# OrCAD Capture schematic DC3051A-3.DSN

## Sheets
1 PAGE2: size A
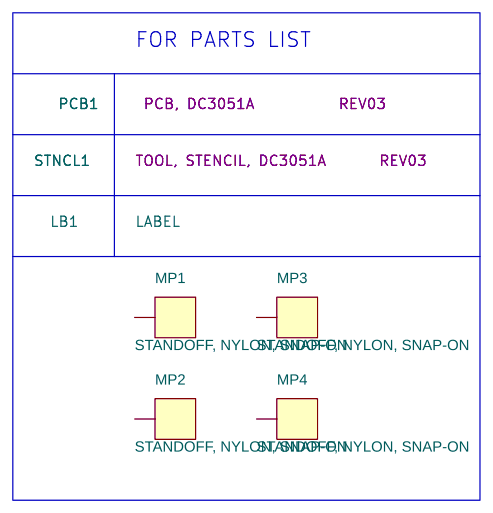
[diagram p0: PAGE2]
2 PAGE1: size Custom; title: Switched Capacitor Converter; company: ANALOG DEVICES; note: DEMO BOARD BILL OF MATERIALS; note: 20Vin,Dual 5A Step-Down DC/DC    Module    Regulator
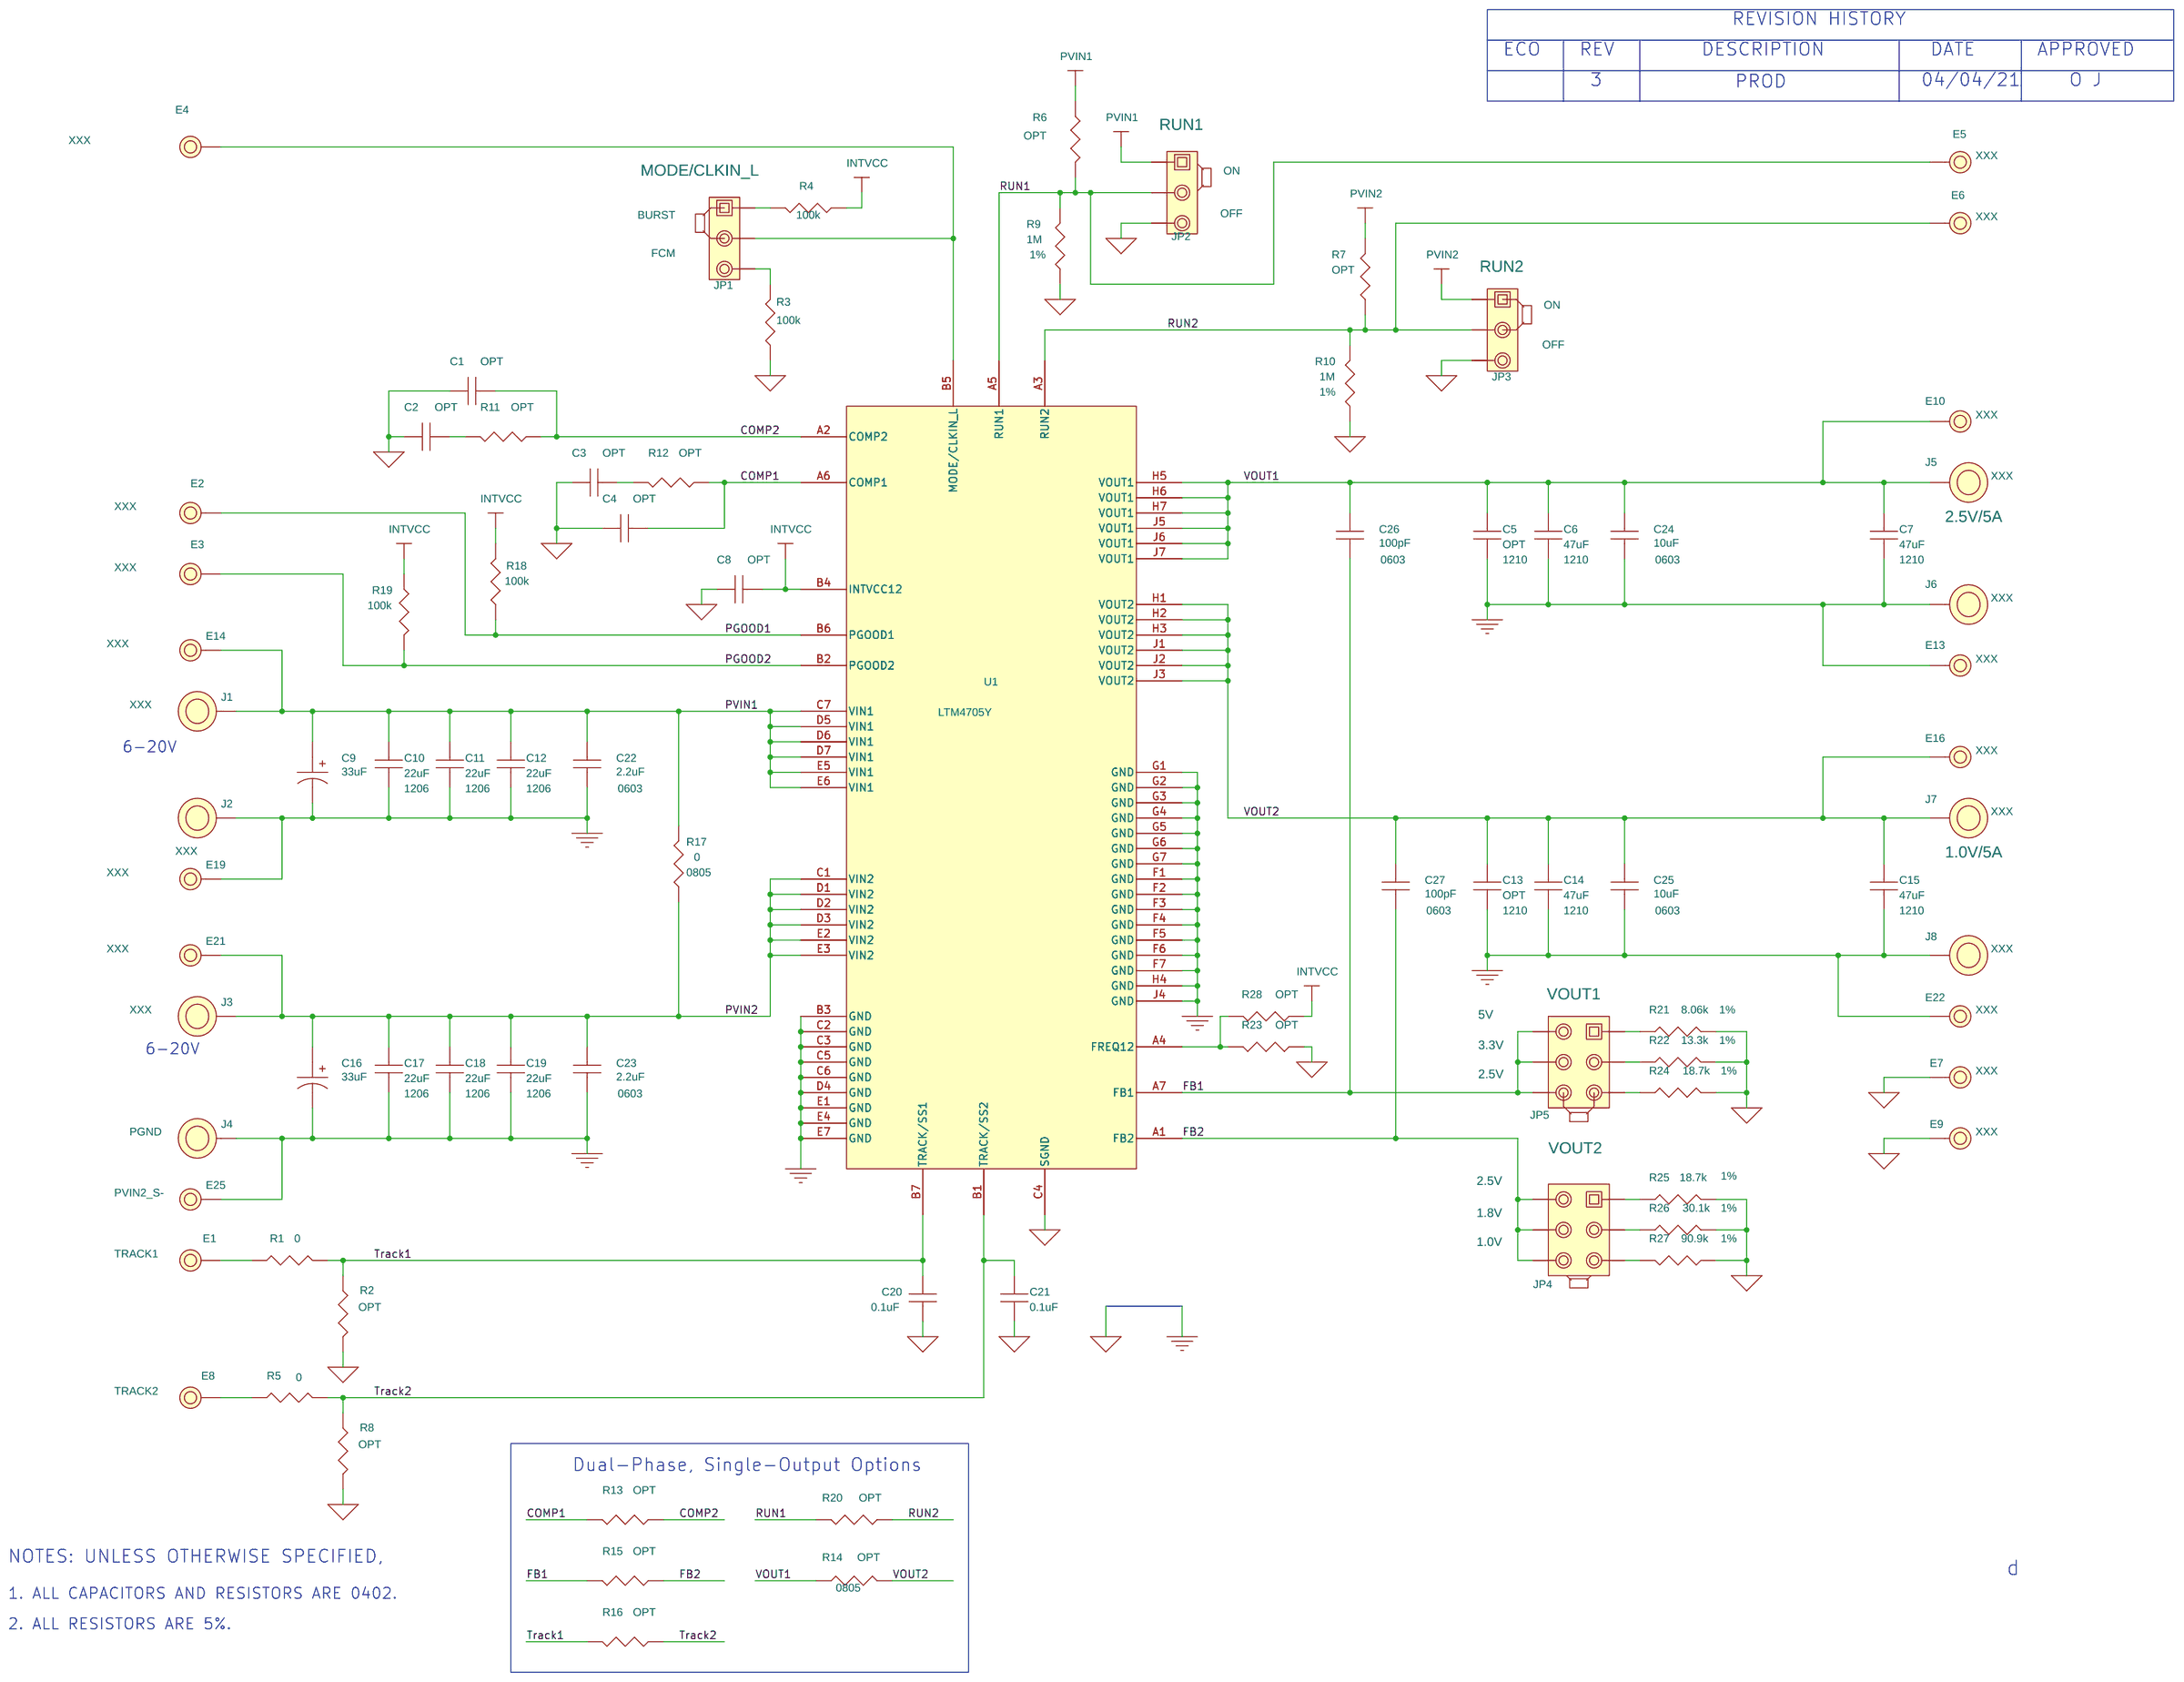
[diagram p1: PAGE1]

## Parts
sheet PAGE1
C1  OPT  [CC0402N]
C2  OPT  [CC0402N]
C3  OPT  [CC0402N]
C4  OPT  [CC0402N]
C5  OPT  [CC1210N]
C6  47uF  [CC1210N]
C7  47uF  [CC1210N]
C8  OPT  [CC0402N]
C9  33uF  [SUNCON_CE-FS_6.3X7.7]
C10  22uF  [CC1206N]
C11  22uF  [CC1206N]
C12  22uF  [CC1206N]
C13  OPT  [CC1210N]
C14  47uF  [CC1210N]
C15  47uF  [CC1210N]
C16  33uF  [SUNCON_CE-FS_6.3X7.7]
C17  22uF  [CC1206N]
C18  22uF  [CC1206N]
C19  22uF  [CC1206N]
C20  0.1uF  [CC0402N]
C21  0.1uF  [CC0402N]
C22  2.2uF  [CC0603N]
C23  2.2uF  [CC0603N]
C24  10uF  [CC0603N]
C25  10uF  [CC0603N]
C26  100pF  [CC0603N]
C27  100pF  [CC0603N]
E1  TEST POINT  [MILLMAX2501]
E2  TEST POINT  [MILLMAX2501]
E3  TEST POINT  [MILLMAX2501]
E4  TEST POINT  [MILLMAX2501]
E5  TEST POINT  [MILLMAX2501]
E6  TEST POINT  [MILLMAX2501]
E7  TEST POINT  [MILLMAX2501]
E8  TEST POINT  [MILLMAX2501]
E9  TEST POINT  [MILLMAX2501]
E10  TEST POINT  [MILLMAX2501]
E13  TEST POINT  [MILLMAX2501]
E14  TEST POINT  [MILLMAX2501]
E16  TEST POINT  [MILLMAX2501]
E19  TEST POINT  [MILLMAX2501]
E21  TEST POINT  [MILLMAX2501]
E22  TEST POINT  [MILLMAX2501]
E25  TEST POINT  [MILLMAX2501]
J1  BANANA JACK  [KEY-575-4]
J2  BANANA JACK  [KEY-575-4]
J3  BANANA JACK  [KEY-575-4]
J4  BANANA JACK  [KEY-575-4]
J5  BANANA JACK  [KEY-575-4]
J6  BANANA JACK  [KEY-575-4]
J7  BANANA JACK  [KEY-575-4]
J8  BANANA JACK  [KEY-575-4]
JP1  HDR  [HD1X3-079]
JP2  HDR  [HD1X3-079]
JP3  HDR  [HD1X3-079]
JP4  HDR  [HD2X3-079]
JP5  HDR  [HD2X3-079]
R1  0  [CR0402N]
R2  OPT  [CR0402N]
R3  100k  [CR0402N]
R4  100k  [CR0402N]
R5  0  [CR0402N]
R6  OPT  [CR0402N]
R7  OPT  [CR0402N]
R8  OPT  [CR0402N]
R9  1M  [CR0402N]
R10  1M  [CR0402N]
R11  OPT  [CR0402N]
R12  OPT  [CR0402N]
R13  OPT  [CR0402N]
R14  OPT  [CR0805N]
R15  OPT  [CR0402N]
R16  OPT  [CR0402N]
R17  0  [CR0805N]
R18  100k  [CR0402N]
R19  100k  [CR0402N]
R20  OPT  [CR0402N]
R21  8.06k  [CR0402N]
R22  13.3k  [CR0402N]
R23  OPT  [CR0402N]
R24  18.7k  [CR0402N]
R25  18.7k  [CR0402N]
R26  30.1k  [CR0402N]
R27  90.9k  [CR0402N]
R28  OPT  [CR0402N]
U1  LTM4705Y  [LTC-LGA-63-XXXX]
XJP1  SHUNT
XJP2  SHUNT
XJP3  SHUNT
XJP4  SHUNT
XJP5  SHUNT
sheet PAGE2
LB1  LABEL  [895-0154_REV01]
MP1  STANDOFF, NYLON, SNAP-ON  [KEYSTONE_8829-8834]
MP2  STANDOFF, NYLON, SNAP-ON  [KEYSTONE_8829-8834]
MP3  STANDOFF, NYLON, SNAP-ON  [KEYSTONE_8829-8834]
MP4  STANDOFF, NYLON, SNAP-ON  [KEYSTONE_8829-8834]
PCB1  PCB, DC3051A
STNCL1  TOOL, STENCIL, DC3051A

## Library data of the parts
C1-C4 C8 = CAP: CAP., OPTION, 0402; CLASS: DISCRETE; FPLIST: CC0402N,CC0402L,CC0402M; PART_NUMBER: 150-3148; Package Size: 0402; Package Type: SMD
C5 C13 = CAP: CAP., OPTION, 1210; CLASS: DISCRETE; FPLIST: CC1210N,CC1210L,CC1210M; PART_NUMBER: 150-3035; Package Size: 1210; Package Type: SMD
C6 C7 C14 C15 = CAP: CAP.,47uF,X7R,10V,20%,1210; CLASS: DISCRETE; Dielectric Type: X7R; FPLIST: CC1210N,CC1210L,CC1210M; Inventory Qty: 3000; Manufacturer: MURATA; Manufacturer PN: GRM32ER71A476ME15L; PART_NUMBER: 150-3224; Package Size: 1210; Rated Voltage: 10V; Tolerance: 20%
C9 C16 = CAP_P: CAP.,33uF,ALUM. ELECT.,50V,20%,6.3mmX7.7mm; CLASS: DISCRETE; Dielectric Type: ALUM. ELECT.; Inventory Qty: 4500; Manufacturer: SUN ELECTRONIC INDUSTRIES CORP; Manufacturer PN: 50CE33FS; PART_NUMBER: 150-2487; Package Size: 6.3mmX7.7mm; Rated Voltage: 50V; Tolerance: 20%
C10-C12 C17-C19 = CAP: CAP.,22uF,X5R,35V,20%,1206; CLASS: DISCRETE; Dielectric Type: X5R; FPLIST: CC1206N,CC1206L,CC1206M; Inventory Qty: 5000; Manufacturer: TDK; Manufacturer PN: C3216X5R1V226M160AC; PART_NUMBER: 150-2384; Package Size: 1206; Package Type: Surface Mount, MLCC; Rated Voltage: 35V; Temperature Coefficient: X5R; Tolerance: 20%
C20 C21 = CAP: CAP.,0.1uF,X7R,25V,10%,0402,AEC-Q200; CLASS: DISCRETE; Dielectric Type: X7R; FPLIST: CC0402N,CC0402L,CC0402M; Inventory Qty: 22030; Manufacturer: MURATA; Manufacturer PN: GCM155R71E104KE02D; PART_NUMBER: 150-1756; Package Size: 0402; Rated Voltage: 25V; Temperature Coefficient: X7R; Tolerance: 10%
C22 C23 = CAP: CAP.,2.2uF,X5R,35V,10%,0603; CLASS: DISCRETE; Dielectric Type: X5R; FPLIST: CC0603N,CC0603L,CC0603M; Inventory Qty: 3900; Manufacturer: MURATA; Manufacturer PN: GRM188R6YA225KA12D; PART_NUMBER: 150-1671; Package Size: 0603; Rated Voltage: 35V; Tolerance: 10%
C24 C25 = CAP: CAP.,10uF,X5R,10V,10%,0603; CLASS: DISCRETE; Dielectric Type: X5R; FPLIST: CC0603N,CC0603L,CC0603M; Inventory Qty: 23010; Manufacturer: AVX; Manufacturer PN: 0603ZD106KAT2A; PART_NUMBER: 150-0576; Package Size: 0603; Rated Voltage: 10V; Tolerance: 10%
C26 C27 = CAP: CAP.,100pF,X7R,50V,10%,0603; CLASS: DISCRETE; Dielectric Type: X7R; FPLIST: CC0603N,CC0603L,CC0603M; Inventory Qty: 49853; Manufacturer: AVX; Manufacturer PN: 06035C101KAT2A; PART_NUMBER: 150-3220; Package Size: 0603; Rated Voltage: 50V; Tolerance: 10%
E1 = TESTPOINT_.219_MILL-MAX_2501: TEST POINT,TURRET,0.094" MTG. HOLE,PCB 0.062" THK; CLASS: IO; FPLIST: MILLMAX2501,MILLMAX2501-2; Inventory Qty: 823526; Manufacturer: MILL-MAX; Manufacturer PN: 2501-2-00-80-00-00-07-0; PART_NUMBER: 260-0003; TEXT: TRACK1
E2-E7 E9 E10 E13 E14 E16 E19 E21 E22 = TESTPOINT_.219_MILL-MAX_2501: TEST POINT,TURRET,0.094" MTG. HOLE,PCB 0.062" THK; CLASS: IO; FPLIST: MILLMAX2501,MILLMAX2501-2; Inventory Qty: 823526; Manufacturer: MILL-MAX; Manufacturer PN: 2501-2-00-80-00-00-07-0; PART_NUMBER: 260-0003; TEXT: XXX
E8 = TESTPOINT_.219_MILL-MAX_2501: TEST POINT,TURRET,0.094" MTG. HOLE,PCB 0.062" THK; CLASS: IO; FPLIST: MILLMAX2501,MILLMAX2501-2; Inventory Qty: 823526; Manufacturer: MILL-MAX; Manufacturer PN: 2501-2-00-80-00-00-07-0; PART_NUMBER: 260-0003; TEXT: TRACK2
E25 = TESTPOINT_.219_MILL-MAX_2501: TEST POINT,TURRET,0.094" MTG. HOLE,PCB 0.062" THK; CLASS: IO; FPLIST: MILLMAX2501,MILLMAX2501-2; Inventory Qty: 823526; Manufacturer: MILL-MAX; Manufacturer PN: 2501-2-00-80-00-00-07-0; PART_NUMBER: 260-0003; TEXT: PVIN2_S-
J1-J3 J6 J8 = BANANA_KEYSTONE-575-4: CONN.,BANANA JACK,FEMALE,THT,NON-INSULATED,SWAGE,0.218"; CLASS: IO; Inventory Qty: 203061; Manufacturer: KEYSTONE; Manufacturer PN: 575-4; PART_NUMBER: 250-0428; TEXT: XXX
J4 = BANANA_KEYSTONE-575-4: CONN.,BANANA JACK,FEMALE,THT,NON-INSULATED,SWAGE,0.218"; CLASS: IO; Inventory Qty: 203061; Manufacturer: KEYSTONE; Manufacturer PN: 575-4; PART_NUMBER: 250-0428; TEXT: PGND
J5 = BANANA_KEYSTONE-575-4: CONN.,BANANA JACK,FEMALE,THT,NON-INSULATED,SWAGE,0.218"; 5TH PART FIELD: 2.5V/5A; CLASS: IO; Inventory Qty: 203061; Manufacturer: KEYSTONE; Manufacturer PN: 575-4; PART_NUMBER: 250-0428; TEXT: XXX
J7 = BANANA_KEYSTONE-575-4: CONN.,BANANA JACK,FEMALE,THT,NON-INSULATED,SWAGE,0.218"; 5TH PART FIELD: 1.0V/5A; CLASS: IO; Inventory Qty: 203061; Manufacturer: KEYSTONE; Manufacturer PN: 575-4; PART_NUMBER: 250-0428; TEXT: XXX
JP1 = 1X3_A: CONN.,HDR,MALE,1x3,2mm,VERT,ST,THT,NO SUBS. ALLOWED; 11th Part Field: FCM; 12th Part Field: MODE/CLKIN_L; 9th Part Field: BURST; CLASS: IO; Inventory Qty: 28997; Manufacturer: Wurth Elektronik; Manufacturer PN: 62000311121; PART_NUMBER: 250-0639; Part Number: WURTH 620 003 111 21
JP2 = 1X3_A: CONN.,HDR,MALE,1x3,2mm,VERT,ST,THT,NO SUBS. ALLOWED; 11th Part Field: ON; 12th Part Field: RUN1; 9th Part Field: OFF; CLASS: IO; Inventory Qty: 28997; Manufacturer: Wurth Elektronik; Manufacturer PN: 62000311121; PART_NUMBER: 250-0639; Part Number: WURTH 620 003 111 21
JP3 = 1X3_A: CONN.,HDR,MALE,1x3,2mm,VERT,ST,THT,NO SUBS. ALLOWED; 11th Part Field: ON; 12th Part Field: RUN2; 9th Part Field: OFF; CLASS: IO; Inventory Qty: 28997; Manufacturer: Wurth Elektronik; Manufacturer PN: 62000311121; PART_NUMBER: 250-0639; Part Number: WURTH 620 003 111 21
JP4 = HDR2X3_ALT1: CONN.,HDR,MALE,2x3,2mm,VERT,ST,THT; 5TH PART FIELD: VOUT2; CLASS: IO; Inventory Qty: 28346; Lbl1: 2.5V; Lbl3: 1.0V; Manufacturer: SULLINS CONNECTOR SOLUTIONS; Manufacturer PN: NRPN032PAEN-RC; PART_NUMBER: 250-0430; lbl2: 1.8V
JP5 = HDR2X3_ALT1: CONN.,HDR,MALE,2x3,2mm,VERT,ST,THT; 5TH PART FIELD: VOUT1; CLASS: IO; Inventory Qty: 28346; Lbl1: 5V; Lbl3: 2.5V; Manufacturer: SULLINS CONNECTOR SOLUTIONS; Manufacturer PN: NRPN032PAEN-RC; PART_NUMBER: 250-0430; lbl2: 3.3V
R1 R5 = RES: RES.,0 OHM,1/10W,0402,AEC-Q200; CLASS: DISCRETE; FPLIST: CR0402N,CR0402L,CR0402M; Inventory Qty: 32994; Manufacturer: PANASONIC; Manufacturer PN: ERJ2GE0R00X; PART_NUMBER: 100-2408; Package Size: 0402; Rated Power: 1/10W
R2 R6-R8 R11-R13 R15 R16 R20 R23 R28 = RES: RES., OPTION, 0402; CLASS: DISCRETE; FPLIST: CR0402N,CR0402L,CR0402M; PART_NUMBER: 100-0357; Package Size: 0402
R3 R4 = RES: RES.,100k OHMS,5%,1/16W,0402,AEC-Q200; CLASS: DISCRETE; FPLIST: CR0402N,CR0402L,CR0402M; Inventory Qty: 10000; Manufacturer: ROHM; Manufacturer PN: MCR01MZPJ104; PART_NUMBER: 100-0192; Package Size: 0402; Rated Power: 1/16W; Temperature Coefficient: 200ppm/C; Tolerance: 5%
R9 R10 = RES: RES.,1M OHM,1%,1/16W,0402,AEC-Q200; CLASS: DISCRETE; FPLIST: CR0402N,CR0402L,CR0402M; Inventory Qty: 86432; Manufacturer: STACKPOLE ELECTRONICS, INC.; Manufacturer PN: RMCF0402FT1M00; PART_NUMBER: 100-2457; Package Size: 0402; Rated Power: 1/16W; Temperature Coefficient: 100ppm; Tolerance: 1%
R14 = RES: RES., OPTION, 0805; CLASS: DISCRETE; FPLIST: CR0805N,CR0805L,CR0805M; PART_NUMBER: 100-2558; Package Size: 0805
R17 = RES: RES.,0 OHMS,JUMPER,0805; CLASS: DISCRETE; FPLIST: VISHAY-WSL0805,CR0805N,CR0805L,CR0805M; Inventory Qty: 5000; Manufacturer: VISHAY; Manufacturer PN: WSL080500000ZEA9; PART_NUMBER: 100-1704; Package Size: 0805; Temperature Coefficient: +/-3900ppm; Tolerance: JUMPER
R18 R19 = RES: RES.,100k OHMS,5%,1/16W,0402,AEC-Q200; CLASS: DISCRETE; FPLIST: CR0402N,CR0402L,CR0402M; Inventory Qty: 59032; Manufacturer: NIC; Manufacturer PN: NRC04J104TRF; PART_NUMBER: 100-0359; Package Size: 0402; Rated Power: 1/16W; Temperature Coefficient: 200ppm/C; Tolerance: 5%
R21 = RES: RES.,8.06k OHMS,1%,1/16W,0402,AEC-Q200; CLASS: DISCRETE; FPLIST: CR0402N,CR0402L,CR0402M; Inventory Qty: 53075; Manufacturer: NIC; Manufacturer PN: NRC04F8061TRF; PART_NUMBER: 100-2983; Package Size: 0402; Rated Power: 1/16W; Temperature Coefficient: +/-100PPM; Tolerance: 1%
R22 = RES: RES.,13.3k OHMS,1%,1/16W,0402,AEC-Q200; CLASS: DISCRETE; FPLIST: CR0402N,CR0402L,CR0402M; Inventory Qty: 39956; Manufacturer: VISHAY; Manufacturer PN: CRCW040213K3FKED; PART_NUMBER: 100-0354; Package Size: 0402; Rated Power: 1/16W; Temperature Coefficient: 100ppm/C; Tolerance: 1%
R24 R25 = RES: RES.,18.7k OHMS,1%,1/16W,0402,AEC-Q200; CLASS: DISCRETE; FPLIST: CR0402N,CR0402L,CR0402M; Inventory Qty: 9922; Manufacturer: VISHAY; Manufacturer PN: CRCW040218K7FKED; PART_NUMBER: 100-0857; Package Size: 0402; Rated Power: 1/16W; Temperature Coefficient: 100ppm; Tolerance: 1%
R26 = RES: RES.,30.1k OHMS,1%,1/16W,0402,AEC-Q200; CLASS: DISCRETE; FPLIST: CR0402N,CR0402L,CR0402M; Inventory Qty: 103026; Manufacturer: NIC; Manufacturer PN: NRC04F3012TRF; PART_NUMBER: 100-2935; Package Size: 0402; Rated Power: 1/16W; Temperature Coefficient: 100ppm; Tolerance: 1%
R27 = RES: RES.,90.9k OHMS,1%,1/16W,0402,AEC-Q200; CLASS: DISCRETE; FPLIST: CR0402N,CR0402L,CR0402M; Inventory Qty: 69492; Manufacturer: NIC; Manufacturer PN: NRC04F9092TRF; PART_NUMBER: 100-2879; Package Size: 0402; Rated Power: 1/16W; Temperature Coefficient: 100ppm; Tolerance: 1%
U1 = LTM4705-LGA: IC,20VIN,Dual 5A Step-Down,63-LGA,PRELIM-NOT FOR PRODUCTION; CLASS: IC; Inventory Qty: 0; Manufacturer: ANALOG DEVICES; Manufacturer PN: LTM4705Y#PBF; PART_NUMBER: LTM4705Y#PBF; Package Size: 6.25mmX7.5mmX2.7mm; Package Type: 63-LGA
XJP1-XJP3 = SHUNT_2MM: CONN.,SHUNT,FEMALE,2 POS,2mm; CLASS: IO; Inventory Qty: 64675; Manufacturer: Wurth Elektronik; Manufacturer PN: 60800213421; PART_NUMBER: 250-0485; Part Number: WURTH ELEKTRONIK 60800213421
XJP4 XJP5 = SHUNT_B: CONN.,SHUNT,FEMALE,2-POS.,2.54mm; CLASS: IO; Inventory Qty: 6809; Manufacturer: WURTH ELEKTRONIK; Manufacturer PN: 60900213421; PART_NUMBER: 250-0526
LB1 = BLANK_LABEL: LABEL SPEC, DEMO BOARD SERIAL NUMBER; Inventory Qty: 0; Manufacturer: BRADY; Manufacturer PN: THT-96-717-10; PART_NUMBER: 895-0154
MP1-MP4 = MP-PINNED: STANDOFF, NYLON, SNAP-ON,0.375"; CLASS: DISCRETE; Inventory Qty: 202920; Manufacturer: KEYSTONE; Manufacturer PN: 8832; PART_NUMBER: 763-0008
PCB1 = BLANK_PCB_PART: BOM Notes: REV03; CLASS: DISCRETE; Inventory Qty: 0; Manufacturer: ADI APPROVED SUPPLIER; Manufacturer PN: 600-DC3051A; PART_NUMBER: 600-DC3051A
STNCL1 = BLANK_STENCIL_PART: BOM Notes: REV03; CLASS: DISCRETE; Inventory Qty: 0; Manufacturer: ADI APPROVED SUPPLIER; Manufacturer PN: 830-DC3051A; PART_NUMBER: 830-DC3051A

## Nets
GND_POWER: C5.2 C6.2 C7.2 C9.2 C10.2 C11.2 C12.2 C13.2 C14.2 C15.2 C16.2 C17.2 C18.2 C19.2 C22.2 C23.2 C24.2 C25.2 E13.1 E19.1 E22.1 E25.1 J2.1 J4.1 J6.1 J8.1 U1.B3(GND) U1.C2(GND) U1.C3(GND) U1.C5(GND) U1.C6(GND) U1.D4(GND) U1.E1(GND) U1.E4(GND) U1.E7(GND) U1.F1(GND) U1.F2(GND) U1.F3(GND) U1.F4(GND) U1.F5(GND) U1.F6(GND) U1.F7(GND) U1.G1(GND) U1.G2(GND) U1.G3(GND) U1.G4(GND) U1.G5(GND) U1.G6(GND) U1.G7(GND) U1.H4(GND) U1.J4(GND)
GND_SIGNAL: C1.1 C2.1 C3.1 C4.1 C8.1 C20.2 C21.2 E7.1 E9.1 JP2.3 JP3.3 R2.2 R3.1 R8.2 R9.2 R10.2 R21.2 R22.2 R23.1 R24.2 R25.2 R26.2 R27.2 U1.C4(SGND)
PVIN1: C9.1 C10.1 C11.1 C12.1 C22.1 E14.1 J1.1 JP2.1 R6.1 R17.1 U1.C7(VIN1) U1.D5(VIN1) U1.D6(VIN1) U1.D7(VIN1) U1.E5(VIN1) U1.E6(VIN1)
PVIN2: C16.1 C17.1 C18.1 C19.1 C23.1 E21.1 J3.1 JP3.1 R7.1 R17.2 U1.C1(VIN2) U1.D1(VIN2) U1.D2(VIN2) U1.D3(VIN2) U1.E2(VIN2) U1.E3(VIN2)
COMP1: C4.2 R12.1 R13.2 U1.A6(COMP1)
COMP2: C1.2 R11.1 R13.1 U1.A2(COMP2)
FB1: C26.2 JP5.2 JP5.4 JP5.6 R15.2 U1.A7(FB1)
FB2: C27.2 JP4.2 JP4.4 JP4.6 R15.1 U1.A1(FB2)
INTvcc: C8.2 R4.2 R18.1 R19.2 R28.1 U1.B4(INTVCC12)
PGOOD1: E2.1 R18.2 U1.B6(PGOOD1)
PGOOD2: E3.1 R19.1 U1.B2(PGOOD2)
RUN1: E5.1 JP2.2 R6.2 R9.1 R20.2 U1.A5(RUN1)
RUN2: E6.1 JP3.2 R7.2 R10.1 R20.1 U1.A3(RUN2)
Track1: C20.1 R1.2 R2.1 R16.2 U1.B7(TRACK/SS1)
Track2: C21.1 R5.2 R8.1 R16.1 U1.B1(TRACK/SS2)
VOUT1: C5.1 C6.1 C7.1 C24.1 C26.1 E10.1 J5.1 R14.1 U1.H5(VOUT1) U1.H6(VOUT1) U1.H7(VOUT1) U1.J5(VOUT1) U1.J6(VOUT1) U1.J7(VOUT1)
VOUT2: C13.1 C14.1 C15.1 C25.1 C27.1 E16.1 J7.1 R14.2 U1.H1(VOUT2) U1.H2(VOUT2) U1.H3(VOUT2) U1.J1(VOUT2) U1.J2(VOUT2) U1.J3(VOUT2)
N23596: JP1.3 R3.2
N23736: JP1.1 R4.1
N41182: C3.2 R12.2
N41411: C2.2 R11.2
N59796: E4.1 JP1.2 U1.B5(MODE/CLKIN_L)
N130427: R23.2 R28.2 U1.A4(FREQ12)
N132280: E8.1 R5.1
N132282: E1.1 R1.1
N172959: JP4.1 R25.1
N172963: JP4.3 R26.1
N172967: JP4.5 R27.1
N173571: JP5.1 R21.1
N173575: JP5.3 R22.1
N173579: JP5.5 R24.1

Not connected (* = marked no-connect by the designer): MP1 1; MP2 1; MP3 1; MP4 1

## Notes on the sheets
sheet 1
- FOR PARTS LIST
sheet 2
- REVISION HISTORY
- ECO
- REV
- DESCRIPTION
- DATE
- APPROVED
- 3
- PROD
- 04/04/21
- O J
- 6-20V
- 6-20V
- Dual-Phase, Single-Output Options
- NOTES: UNLESS OTHERWISE SPECIFIED,
- d
- 1. ALL CAPACITORS AND RESISTORS ARE 0402.
- 2. ALL RESISTORS ARE 5%.
